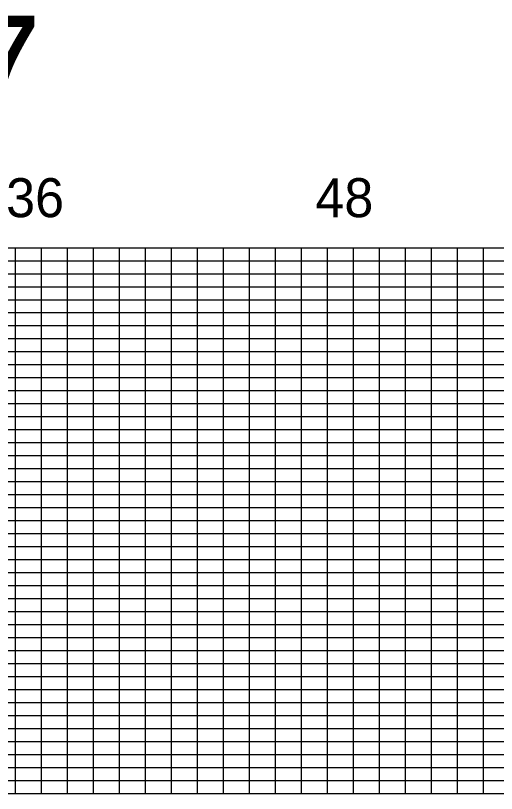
# Model space of a CAD drawing. Extents: x 1894907 to 1905782, y 740939 to 777025.
# Drawn here: x 1897382 to 1898307, y 760864 to 762361 of the extents above; entities that cross this region are included whole.
import ezdxf

# ---------------------------------------------------------------- set-up
doc = ezdxf.new("R2010")
doc.units = 0
doc.layers.add('RD_PD_WallFill', color=7, linetype='Continuous')
doc.layers.add('RD_Sketch8', color=7, linetype='Continuous')

msp = doc.modelspace()

# ---------------------------------------------------------------- linework, layer by layer
at = {"layer": 'RD_PD_WallFill'}
for p, q in [((1895631.6, 761914.1), (1900981.6, 761914.1)), ((1897381.6, 760864.1), (1897381.6, 761914.1)), ((1897431.6, 760864.1), (1897431.6, 761914.1)), ((1897481.6, 760864.1), (1897481.6, 761914.1)), ((1897531.6, 760864.1), (1897531.6, 761914.1)), ((1897581.6, 760864.1), (1897581.6, 761914.1)), ((1897631.6, 760864.1), (1897631.6, 761914.1)), ((1897681.6, 760864.1), (1897681.6, 761914.1)), ((1897731.6, 760864.1), (1897731.6, 761914.1)), ((1897781.6, 760864.1), (1897781.6, 761914.1)), ((1897831.6, 760864.1), (1897831.6, 761914.1)), ((1897881.6, 760864.1), (1897881.6, 761914.1)), ((1897931.6, 760864.1), (1897931.6, 761914.1)), ((1897981.6, 760864.1), (1897981.6, 761914.1)), ((1898031.6, 760864.1), (1898031.6, 761914.1)), ((1898081.6, 760864.1), (1898081.6, 761914.1)), ((1898131.6, 760864.1), (1898131.6, 761914.1)), ((1898181.6, 760864.1), (1898181.6, 761914.1)), ((1898231.6, 760864.1), (1898231.6, 761914.1)), ((1898281.6, 760864.1), (1898281.6, 761914.1)), ((1896081.6, 761889.1), (1900981.6, 761889.1)), ((1896081.6, 761864.1), (1900981.6, 761864.1)), ((1896081.6, 761839.1), (1900981.6, 761839.1)), ((1896081.6, 761814.1), (1900981.6, 761814.1)), ((1896081.6, 761789.1), (1900981.6, 761789.1)), ((1895631.6, 761764.1), (1900981.6, 761764.1)), ((1895631.6, 761739.1), (1900981.6, 761739.1)), ((1895631.6, 761714.1), (1900981.6, 761714.1)), ((1895631.6, 761689.1), (1900981.6, 761689.1)), ((1895631.6, 761664.1), (1900981.6, 761664.1)), ((1895631.6, 761639.1), (1900981.6, 761639.1)), ((1895631.6, 761614.1), (1900981.6, 761614.1)), ((1895631.6, 761589.1), (1900981.6, 761589.1)), ((1895631.6, 761564.1), (1900981.6, 761564.1)), ((1895631.6, 761539.1), (1900981.6, 761539.1)), ((1895631.6, 761514.1), (1900981.6, 761514.1)), ((1895631.6, 761489.1), (1900981.6, 761489.1)), ((1895631.6, 761464.1), (1900981.6, 761464.1)), ((1895631.6, 761439.1), (1900981.6, 761439.1)), ((1895631.6, 761414.1), (1900981.6, 761414.1)), ((1895631.6, 761389.1), (1900981.6, 761389.1)), ((1895631.6, 761364.1), (1900981.6, 761364.1)), ((1895631.6, 761339.1), (1900981.6, 761339.1)), ((1895631.6, 761314.1), (1900981.6, 761314.1)), ((1895631.6, 761289.1), (1900981.6, 761289.1)), ((1895631.6, 761264.1), (1900981.6, 761264.1)), ((1895631.6, 761239.1), (1900981.6, 761239.1)), ((1895631.6, 761214.1), (1900981.6, 761214.1)), ((1895631.6, 761189.1), (1900981.6, 761189.1)), ((1895631.6, 761164.1), (1900981.6, 761164.1)), ((1895631.6, 761139.1), (1900981.6, 761139.1)), ((1895631.6, 761114.1), (1900981.6, 761114.1)), ((1895631.6, 761089.1), (1900981.6, 761089.1)), ((1895631.6, 761064.1), (1900981.6, 761064.1)), ((1895631.6, 761039.1), (1900981.6, 761039.1)), ((1895631.6, 761014.1), (1900981.6, 761014.1)), ((1895631.6, 760989.1), (1900981.6, 760989.1)), ((1895631.6, 760964.1), (1900981.6, 760964.1)), ((1895631.6, 760939.1), (1900981.6, 760939.1)), ((1895631.6, 760914.1), (1900981.6, 760914.1)), ((1895681.6, 760889.1), (1900981.6, 760889.1)), ((1895631.6, 760864.1), (1900981.6, 760864.1))]:
    msp.add_line(p, q, dxfattribs=at)

# ---------------------------------------------------------------- texts
for s, p in [('22x36', (1897201.7, 761972.8)), ('48', (1897958.3, 761972.8))]:
    msp.add_text(s, height=75, dxfattribs=at).set_placement(p)
at = {"layer": 'RD_Sketch8'}
msp.add_text('7', height=200, dxfattribs=at).set_placement((1897282.7, 762160.7))

doc.saveas('drawing.dxf')
